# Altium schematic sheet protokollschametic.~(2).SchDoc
size A4
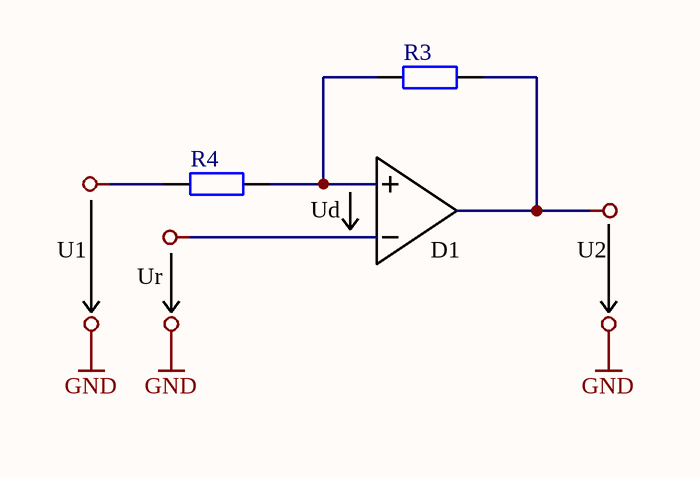
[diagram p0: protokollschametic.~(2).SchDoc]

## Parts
R3  Res2  [AXIAL-0.4]  (value not drawn)
R4  Res2  [AXIAL-0.4]  (value not drawn)

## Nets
GND: R3.2 R4.1
NetR3_1: R3.1 R4.2

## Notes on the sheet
- (near R4) Ud
- U1
- (near R4) Ur
- D1
- U2

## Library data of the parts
R3 R4 = Res2: Resistor; Value: 1K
